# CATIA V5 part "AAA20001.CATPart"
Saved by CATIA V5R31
Part number: AAA20001
Revision: 3
Nomenclature: BRKT_STOPPER
Source: Unknown
Property "部品番号(A社)": "AAA20001"
Property "部品名称(A社)": "BRKT_STOPPER"
Property "Version(A社)": "3"
Property "材質": "JSH270C"
Property "板厚": "2.3"
Bounding box of the stored display mesh (mm): x -504.28 to -484.28, y -29.401 to -19.401, z 448.299 to 463.299
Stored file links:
  \\cad-nas02\CATIA1212\BODY_DEPARTMENT8\JAMA\変換データ\STEP3_最終_20240115\01_いすゞ板金\new_ファイル名修正後\CATIA_V5_20240122\AAA20001.CATPart
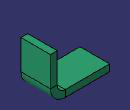
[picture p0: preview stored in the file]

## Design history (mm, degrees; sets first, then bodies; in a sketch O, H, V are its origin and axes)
Body1 "MANIFOLD_SOLID_BREP #326" (main body)
  Solid1: solid without history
